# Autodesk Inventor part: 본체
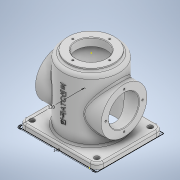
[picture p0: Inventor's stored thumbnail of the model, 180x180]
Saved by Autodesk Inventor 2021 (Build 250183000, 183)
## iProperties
Created: 2021-02
Part Number: 본체
Material: 알루미늄 6061
Document SubType Name: Modeling
Designer: mdu2-97
Density: 2.7 g/cm^3
Appearance: 기본값
Mass: 1251.31 g
Surface Area: 1080.97 cm^2
Volume: 463.448 cm^3
Author: mdu2-97
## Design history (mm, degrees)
sketch "스케치1"
  geometry: L1 (-70, -60)-(70, -60); L2 (70, -60)-(70, 60); L3 (70, 60)-(-70, 60); L4 (-70, 60)-(-70, -60); L5 (-70, -60)-(70, 60); L6 (70, -60)-(-70, 60); 1 further point
  constraints: 12 end point, 2 midpoint, 2 parallel, 1 horizontal, 1 perpendicular
  dimensions: "d0" = 140 distance of L3.end L2.end; "d1" = 120 distance of L2.end L1.end
extrude "돌출1" new body sketch "스케치1" distance "d2" = 10; taper "d3" = 0 deg
sketch "스케치2"
  geometry: 1 further point
sketch "스케치3"
  geometry: C1 r 50 at (0, 0); 1 further point
  constraints: 1 centre point, 1 coincident
  dimensions: "d4" = 100 diameter of C1
extrude "돌출2" join sketch "스케치3" distance "d5" = 110; taper "d6" = 0 deg
sketch "스케치6"
  geometry: 1 further point
sketch "스케치7"
  geometry: C1 r 27 at (0, 0); 1 further point
  constraints: 1 centre point, 1 coincident
  dimensions: "d12" = 54 diameter of C1
extrude "돌출4" cut sketch "스케치7" distance "d13" = 9; taper "d14" = 0 deg
sketch "스케치8"
  geometry: C1 r 42 at (0, 0); 1 further point
  constraints: 1 centre point, 1 coincident
  dimensions: "d15" = 84 diameter of C1
extrude "돌출5" cut sketch "스케치8" extent not by distance; stored distance "d16" = 0; taper "d17" = 0 deg
sketch "스케치9"
  geometry: C1 r 41 at (0, 0); 1 further point
  constraints: 1 centre point, 1 coincident
  dimensions: "d18" = 82 diameter of C1
extrude "돌출6" join sketch "스케치9" distance "d19" = 5; taper "d20" = 0 deg
sketch "스케치10"
  geometry: C1 r 27 at (0, 0) reference; 1 further point
extrude "돌출7" cut sketch "스케치10" extent not by distance; stored distance "d21" = 5; taper "d22" = 0 deg
fillet "모깎기1" dims "d23" = 6
fillet "모깎기2" dims "d24" = 3
node "작업 평면1"
sketch "스케치11"
  geometry: L1 (10, 60)-(10, -60) reference; L2 (125, -41)-(125, 41) reference; L3 (0, 60)-(0, -60) reference; L4 (10, 50)-(10, -50) reference; L5 (114, -50)-(114, 50) reference; L6 (114, 0)-(10, 0); C1 r 41 at (60, 0); 1 further point
  constraints: 2 end point, 2 midpoint, 1 centre point, 1 point on line
  dimensions: "d26" = 82 diameter of C1; "d27" = 60 distance from line of C1.centre L3
extrude "돌출8" join sketch "스케치11" stored distance "d28" = 5; taper "d29" = 0 deg
sketch "스케치12"
  geometry: C1 r 27 at (0, 0); C2 r 41 at (0, 0) reference; 1 further point
  constraints: 1 centre point, 1 coincident
  dimensions: "d30" = 54 diameter of C1
extrude "돌출9" cut sketch "스케치12" stored distance "d31" = 5; taper "d32" = 0 deg
fillet "모깎기3" dims "d33" = 3
sketch "스케치13"
  geometry: 1 further point
fillet "모깎기4" dims "d34" = 12
sketch "스케치14"
  geometry: C1 r 4.5 at (-58, -48); A1 r 12 centre (-58, -48) between (-70, -48) and (-58, -60) reference; A2 r 12 centre (-58, 48) between (-58, 60) and (-70, 48) reference; A3 r 12 centre (58, 48) between (70, 48) and (58, 60) reference; A4 r 12 centre (58, -48) between (58, -60) and (70, -48) reference; 1 further point
  constraints: 1 centre point, 1 coincident
  dimensions: "d35" = 9 diameter of C1
extrude "돌출10" cut sketch "스케치14" extent not by distance; stored distance "d36" = 0; taper "d37" = 0 deg
sketch "스케치15" dims "d38" = 66
  geometry: 3 further points
  constraints: 1 vertical alignment, 2 other
hole "구멍1" sketch "스케치15" at (0, 33) diameter "d39" = 3.242; stored, may be unused: countersink angle "d43" = 90 deg, drill point angle "d45" = 118 deg; dims "d40" = 8, "d41" = 12, "d42" = 2, "d44" = 10
sketch "스케치16" dims "d49" = 66
  geometry: 3 further points
  constraints: 1 coincident, 1 vertical alignment, 2 other
hole "구멍2" sketch "스케치16" at (0, 33) diameter "d50" = 3.242; stored, may be unused: countersink angle "d54" = 90 deg, drill point angle "d56" = 118 deg; dims "d51" = 8, "d52" = 12, "d53" = 2, "d55" = 10
fillet "모깎기5" dims "d60" = 3
chamfer "모따기1" distance "d61" = 1; stored, may be unused: second distance "d62" = 2, angle "d63" = 45 deg
sketch "스케치17"
  geometry: 1 further point
fillet "모깎기6" dims "d64" = 3
fillet "모깎기7" dims "d65" = 3
node "작업 평면3"
sketch "스케치18"
  geometry: L1 (-58, 0)-(58, 0) reference; L2 (0, 151.2)-(0, -25.2) reference; 2 further points
  constraints: 1 point on line, 1 other
  dimensions: "d67" = 66 distance from line of L1 point (0, 66)
feature "엠보싱1" sketch "스케치18" dims "d68" = 1, "d69" = 0
node "솔리드1"
mirror "미러1"
mirror "미러2"
mirror "미러3"
pattern_circular "원형 패턴1" dims angle "d47" = 360 deg
mirror "미러4"
pattern_circular "원형 패턴2" dims angle "d58" = 360 deg
node "투영된 루프1"
node "작업 평면2"
node "투영된 루프2"
feature "A9D066F2-1C7D-4E18-AEED-F7BC21143FA4" dims "d39" = 3.242, "d40" = 8, "d41" = 12, "d42" = 2, "d43" = 90 deg, "d44" = 10, "d45" = 118 deg
other parameters: "d25" = 59
